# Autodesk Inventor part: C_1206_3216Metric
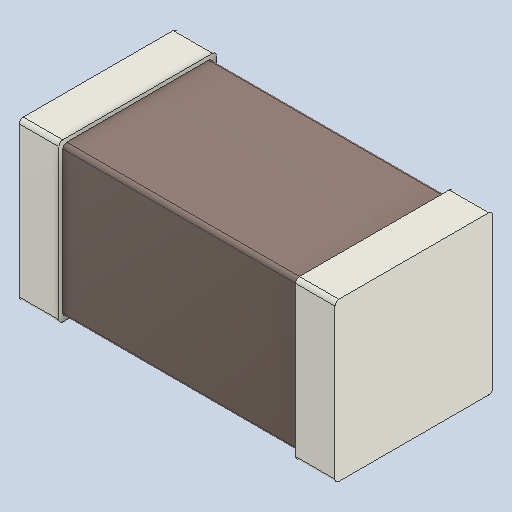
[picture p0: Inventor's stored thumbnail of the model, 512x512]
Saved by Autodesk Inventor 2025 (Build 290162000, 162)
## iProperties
Created: 2026-09
Part Number: C_1206_3216Metric
Material: Generic
Document SubType Name: Modeling
Designer: Leonardo
Density: 1 g/cm^3
Appearance: Default
Author: Leonardo
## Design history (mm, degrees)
feature "Base1"
body "Solid1"
